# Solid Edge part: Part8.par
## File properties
Author: Sham
Template: ansi part.par
Last saved by: Cadcim
Revision: 3
Application: Solid Edge
Accuracy: 0.990
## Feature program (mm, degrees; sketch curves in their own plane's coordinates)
sketch for "unnamed Protrusion 1" plane through (0, 0, 0) normal (0, 0, 1) x-axis (1, 0, 0)
  line (0, 0) -> (114.3, 0)
  line (114.3, 0) -> (114.3, 63.5)
  line (114.3, 63.5) -> (0, 63.5)
  line (0, 63.5) -> (0, 0)
extrude "unnamed Protrusion 1" add finite 47.752 symmetric
sketch for "ExtrudedCutout_1" plane through (0, 31.75, 0) normal (0, -1, 0) x-axis (1, 0, 0)
  line (100.076, 23.876) -> (114.3, 0)
extrude "ExtrudedCutout_1" cut finite 160.7839 symmetric
sketch for "ExtrudedCutout_2" #1 plane through (114.3, 31.75, -11.938) normal (1, 0, 0) x-axis (0, 0, -1)
  line (-35.814, 23.876) -> (-20.066, 23.876)
  line (-20.066, 23.876) -> (-20.066, 31.75)
  line (-20.066, 31.75) -> (-35.814, 31.75)
  line (-35.814, 31.75) -> (-35.814, 23.876)
sketch for "ExtrudedCutout_2" #2 plane through (114.3, 31.75, -11.938) normal (1, 0, 0) x-axis (0, 0, -1)
  line (-35.814, -23.876) -> (-20.066, -23.876)
  line (-20.066, -23.876) -> (-20.066, -31.75)
  line (-20.066, -31.75) -> (-35.814, -31.75)
  line (-35.814, -31.75) -> (-35.814, -23.876)
extrude "ExtrudedCutout_2" cut finite 311.4615 symmetric
sketch for "ExtrudedCutout_13" plane through (39.0327, -43.5173, 10.7275) normal (0.707107, -0.707107, 0) x-axis (0, 0, 1)
  line (23.876, -73.1288) -> (8.128, -88.4254)
  line (8.128, -88.4254) -> (8.128, -78.2905)
  line (8.128, -78.2905) -> (-33.1815, -97.2168)
  line (-33.1815, -97.2168) -> (-33.1815, -114.3)
  line (-33.1815, -114.3) -> (0, -114.3)
  line (0, -114.3) -> (23.876, -93.9932)
  line (23.876, -93.9932) -> (23.876, -73.1288)
extrude "ExtrudedCutout_13" cut finite 140.5799 along +normal
sketch used by "ExtrudedCutout_15" plane through (0, 0, 0) normal (0, 0, 1) x-axis (1, 0, 0)
extrude "ExtrudedCutout_15" cut finite 63.2495 symmetric
sketch for "unnamed Cutout 1" plane through (0, 31.75, 0) normal (0, -1, 0) x-axis (1, 0, 0)
extrude "unnamed Cutout 1" cut finite 316.7054 symmetric
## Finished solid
Body 1: solid body, 12 faces, 30 edges, 20 vertices.
  Faces by surface: plane 12
  Edges by curve: line 30
Bounding box of the edges (mm): 100.076 x 63.500 x 47.752, from (0, 0, -23.876) to (100.076, 63.5, 23.876).
Planar faces by outward normal: +y 2, +z 3, -x 1, -y 2, -z 1, oblique 3
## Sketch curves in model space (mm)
line (114.3, 31.75, 0) -> (99.9409, 17.3909, 23.876)
line (99.9409, 17.3909, 23.876) -> (85.1876, 2.6376, 23.876)
line (85.1876, 2.6376, 23.876) -> (96.0039, 13.4539, 8.128)
line (96.0039, 13.4539, 8.128) -> (88.8374, 6.2874, 8.128)
line (88.8374, 6.2874, 8.128) -> (102.2204, 19.6704, -33.1815)
line (102.2204, 19.6704, -33.1815) -> (114.3, 31.75, -33.1815)
line (114.3, 31.75, -33.1815) -> (114.3, 31.75, 0)
line (125.6727, 0, 2.0896) -> (96.1202, 0, -32.8361)
line (100.076, 31.75, 0) -> (63.2905, 68.5355, 0)
line (100.076, 31.75, 0) -> (63.2905, -5.0355, 0)
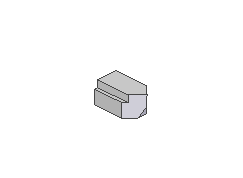
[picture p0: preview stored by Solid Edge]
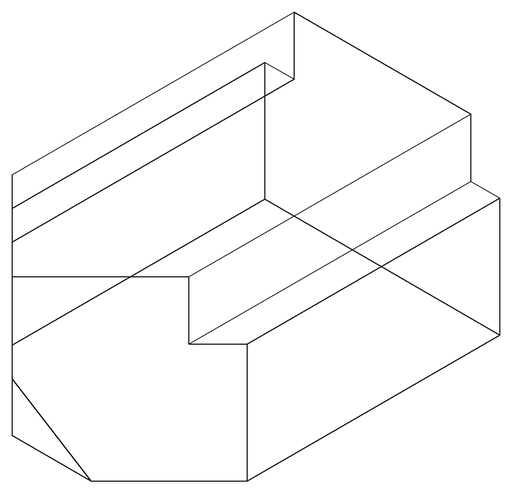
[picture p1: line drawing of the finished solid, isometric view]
